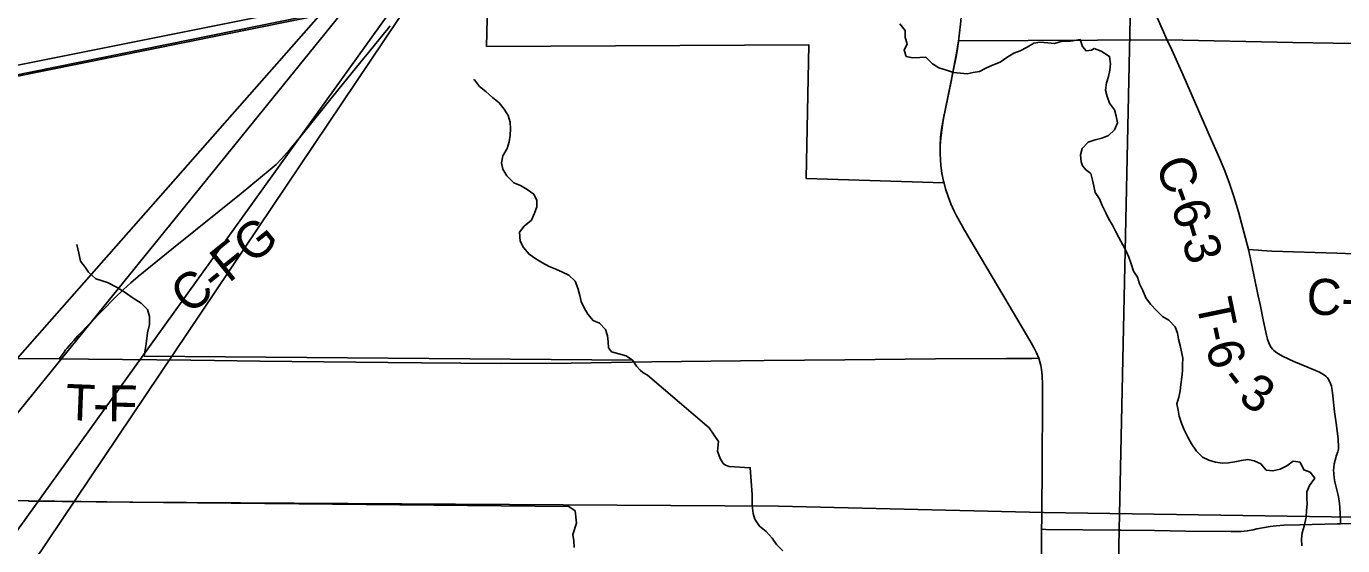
# Model space of a CAD drawing. Extents: x -21.7 to 34, y 0 to 22.
# Drawn here: x 25.914 to 27.989, y 16.19 to 17.008 of the extents above; entities that cross this region are included whole.
import ezdxf

# ---------------------------------------------------------------- set-up
doc = ezdxf.new("R2010")
doc.units = 0
for name, color, linetype in [('GM_X_Corporation', 7, 'Continuous'), ('GM_X_County_Road', 7, 'Continuous'), ('GM_X_County_Road_Text', 7, 'Continuous'), ('GM_X_Interchange_Ramps', 7, 'Continuous'), ('GM_X_Minor_River', 7, 'Continuous'), ('GM_X_Rail_Line', 7, 'Continuous'), ('GM_X_State_Route', 7, 'Continuous'), ('GM_X_Township_Road', 7, 'Continuous'), ('GM_X_Township_Road_Text', 7, 'Continuous'), ('SH_Text', 7, 'Continuous')]:
    doc.layers.add(name, color=color, linetype=linetype)

msp = doc.modelspace()

# ---------------------------------------------------------------- linework, layer by layer
at = {"layer": 'GM_X_Corporation'}
msp.add_lwpolyline([(28.8958, 16.966), (27.9107, 16.9822), (27.7126, 16.9865), (27.3835, 16.9849), (27.3796, 16.9596), (27.3715, 16.9192), (27.3594, 16.8603), (27.3572, 16.8458), (27.3556, 16.8325), (27.3548, 16.82), (27.3546, 16.8075), (27.3557, 16.7888), (27.3575, 16.7765), (27.3607, 16.7612), (27.1434, 16.7683), (27.148, 16.9785), (26.6397, 16.9761), (26.6452, 17.1938)], dxfattribs=at)
at = {"layer": 'GM_X_County_Road'}
for points in [[(27.7128, 16.9859), (27.6888, 17.0394), (27.6756, 17.0676), (27.6712, 17.0758), (27.6677, 17.0811), (27.6658, 17.0835), (27.6636, 17.0859), (27.656, 17.0933)], [(25.966, 16.4842), (25.9737, 16.4944), (25.9762, 16.498), (25.9789, 16.501), (25.9814, 16.5039), (25.9852, 16.5081), (25.9891, 16.513), (25.9953, 16.52), (26.054, 16.5802), (26.0674, 16.5932), (26.0789, 16.6037), (26.0908, 16.6138), (26.1271, 16.6431), (26.1463, 16.6589), (26.253, 16.7446), (26.2987, 16.782), (26.3079, 16.7903), (26.3166, 16.7991), (26.3289, 16.8131), (26.3448, 16.8322), (26.3858, 16.883), (26.4074, 16.9096), (26.4465, 16.9578), (26.4543, 16.967), (26.4788, 16.9973), (26.4827, 17.0017), (26.4876, 17.0083)], [(27.8411, 16.6564), (27.8251, 16.7156), (27.8179, 16.7395), (27.8109, 16.76), (27.8038, 16.7801), (27.7954, 16.8), (27.7824, 16.8284), (27.7626, 16.8741), (27.7381, 16.9308), (27.7203, 16.9706), (27.7128, 16.9859)], [(27.8411, 16.6564), (27.8559, 16.6551), (27.862, 16.6544), (27.8775, 16.6536), (27.9799, 16.6504), (28.0482, 16.6479), (28.0855, 16.6464), (28.2779, 16.6398), (28.3959, 16.636), (28.4673, 16.6333), (28.5636, 16.63), (28.5729, 16.6293), (28.5791, 16.6283), (28.5852, 16.6268), (28.5912, 16.6248), (28.5969, 16.6222), (28.6052, 16.6177), (28.6238, 16.6065), (28.6423, 16.595)], [(25.6331, 16.4875), (25.6723, 16.4872), (25.8993, 16.4845), (25.966, 16.4842)]]:
    msp.add_lwpolyline(points, dxfattribs=at)
at = {"layer": 'GM_X_Interchange_Ramps'}
for points in [[(27.6229, 15.4779), (27.6372, 16.2146), (27.6557, 17.0939)], [(27.6557, 17.0939), (27.6372, 16.2146), (27.6229, 15.4779)]]:
    msp.add_lwpolyline(points, dxfattribs=at)
at = {"layer": 'GM_X_Minor_River'}
for points in [[(27.2913, 17.0115), (27.2998, 17.0011), (27.2999, 16.9901), (27.3027, 16.9801), (27.2983, 16.97), (27.3015, 16.9604), (27.312, 16.9583), (27.3227, 16.9588), (27.3322, 16.959), (27.3429, 16.9485), (27.3527, 16.9422), (27.3662, 16.9381), (27.376, 16.9349), (27.387, 16.9342), (27.3972, 16.9329), (27.4071, 16.9349), (27.417, 16.9366), (27.427, 16.9417)], [(27.427, 16.9417), (27.4374, 16.9468), (27.4492, 16.9514), (27.46, 16.9588), (27.4708, 16.9654), (27.4811, 16.9689), (27.4919, 16.9751), (27.5027, 16.981), (27.5122, 16.983), (27.5247, 16.9816), (27.5353, 16.9806), (27.5456, 16.9838), (27.5608, 16.9846), (27.5753, 16.987), (27.5792, 16.9759), (27.585, 16.969), (27.5934, 16.97)], [(27.588, 16.8251), (27.5991, 16.8291), (27.6098, 16.8315), (27.6201, 16.8359), (27.6297, 16.8448), (27.6345, 16.8557), (27.6324, 16.866), (27.6296, 16.8763), (27.6218, 16.8867), (27.6183, 16.897), (27.6154, 16.907), (27.6172, 16.9187), (27.62, 16.9289), (27.6221, 16.9387), (27.6231, 16.9489), (27.6218, 16.9604), (27.6087, 16.9686), (27.5974, 16.973), (27.5934, 16.97)], [(26.8318, 16.5014), (26.8316, 16.5109), (26.8303, 16.5204), (26.8271, 16.5304), (26.8178, 16.5401), (26.8077, 16.5445), (26.7992, 16.5545), (26.7934, 16.5645), (26.7887, 16.5741), (26.7866, 16.584), (26.7835, 16.5951), (26.7795, 16.6062), (26.7695, 16.6156), (26.7594, 16.6203), (26.7489, 16.6255), (26.7387, 16.6295), (26.7279, 16.6351), (26.7174, 16.6414), (26.7069, 16.6488), (26.6981, 16.6593), (26.6926, 16.6693), (26.6918, 16.6833), (26.6992, 16.693), (26.7108, 16.7026), (26.7153, 16.7136), (26.7193, 16.7237), (26.7188, 16.7336), (26.7144, 16.7432), (26.704, 16.751), (26.6931, 16.7569), (26.6826, 16.7613), (26.6715, 16.7722), (26.6657, 16.783), (26.6636, 16.7929), (26.6654, 16.8039), (26.6721, 16.8151), (26.6754, 16.826), (26.6771, 16.8362), (26.6774, 16.8461), (26.6768, 16.8567), (26.6737, 16.8671), (26.6675, 16.8771), (26.6597, 16.8871), (26.6493, 16.8957), (26.6385, 16.905), (26.6288, 16.9132), (26.6207, 16.9237), (26.6192, 16.9241)], [(27.588, 16.8251), (27.5788, 16.8155), (27.5763, 16.8053), (27.5773, 16.7945), (27.5794, 16.788), (27.5827, 16.7838)], [(27.8399, 16.3257), (27.8297, 16.324), (27.8194, 16.322), (27.8095, 16.3203), (27.7997, 16.3197), (27.7887, 16.3214), (27.7785, 16.3243), (27.7684, 16.3291), (27.7591, 16.3387), (27.751, 16.3499), (27.7452, 16.3607), (27.7397, 16.3722), (27.7354, 16.3829), (27.7318, 16.3936), (27.7301, 16.4031), (27.728, 16.413), (27.7313, 16.4236), (27.7334, 16.4338), (27.7343, 16.4436), (27.7357, 16.455), (27.7366, 16.4649), (27.7368, 16.4744), (27.7374, 16.485), (27.7353, 16.4953), (27.7333, 16.5052), (27.7308, 16.5151), (27.7291, 16.5246), (27.7251, 16.5342), (27.7151, 16.545), (27.7054, 16.5505), (27.6961, 16.5602), (27.6864, 16.5699), (27.679, 16.5799), (27.6744, 16.5918), (27.6689, 16.6021), (27.6657, 16.6125), (27.6598, 16.6221), (27.6559, 16.6335), (27.6523, 16.6442), (27.6479, 16.6538), (27.6428, 16.6634), (27.6366, 16.6749), (27.6315, 16.6849), (27.6264, 16.6945), (27.6209, 16.7041), (27.6162, 16.7141), (27.6103, 16.7256), (27.606, 16.7363), (27.599, 16.7459), (27.5973, 16.7558), (27.5952, 16.7654), (27.5924, 16.7757), (27.5839, 16.7822), (27.5827, 16.7838)], [(26.8696, 16.482), (26.1003, 16.4882), (26.1004, 16.492), (26.1031, 16.5079), (26.1053, 16.5249), (26.1087, 16.5381), (26.1086, 16.5506), (26.1054, 16.5617), (26.0951, 16.5718), (26.0827, 16.5797), (26.07, 16.5887), (26.0573, 16.5966), (26.0423, 16.6041), (26.0239, 16.6102), (26.0123, 16.6203), (26.0072, 16.6284), (25.9998, 16.6381), (25.9971, 16.6503), (25.994, 16.664)], [(26.8599, 16.4887), (26.8369, 16.4953), (26.8318, 16.5014)], [(27.0586, 16.2705), (27.0554, 16.3124), (27.0221, 16.3146), (27.0164, 16.3163), (27.0127, 16.3194), (27.0083, 16.3271), (27.0036, 16.3386), (27.0055, 16.3537), (26.9985, 16.3637), (26.9905, 16.3753), (26.8934, 16.4583), (26.8862, 16.4623), (26.8818, 16.4662), (26.8759, 16.4727), (26.8696, 16.482), (26.8599, 16.4887)], [(27.9248, 16.1896), (27.9242, 16.1999), (27.9255, 16.2097), (27.9284, 16.2203), (27.9317, 16.2347), (27.9323, 16.2449), (27.9333, 16.2551), (27.9327, 16.2646), (27.9329, 16.2745), (27.9369, 16.2843), (27.9454, 16.2959), (27.938, 16.3055), (27.9279, 16.3091), (27.9221, 16.3214), (27.9115, 16.3228), (27.9011, 16.3154), (27.8908, 16.3103), (27.8794, 16.3075), (27.8688, 16.3084), (27.8606, 16.3185), (27.8498, 16.3236), (27.8399, 16.3257)], [(27.1066, 16.1818), (27.097, 16.1915), (27.09, 16.2015), (27.0807, 16.212), (27.0699, 16.2206), (27.0627, 16.2315), (27.06, 16.2406), (27.0586, 16.2529), (27.0586, 16.2705)], [(26.7694, 16.2512), (25.9178, 16.2596)], [(26.7778, 16.1869), (26.7773, 16.1975), (26.7756, 16.2074), (26.7815, 16.2254), (26.7797, 16.2445), (26.7694, 16.2512)]]:
    msp.add_lwpolyline(points, dxfattribs=at)
at = {"layer": 'GM_X_Rail_Line'}
for points in [[(23.5167, 16.459), (23.6295, 16.4808), (23.9621, 16.5465), (24.6321, 16.6797), (25.2774, 16.8081), (25.8901, 16.9293), (26.3845, 17.0293), (27.0776, 17.1675), (27.7467, 17.2984), (28.3715, 17.4275), (28.9889, 17.5495), (29.6221, 17.6814), (30.2791, 17.8098), (30.3167, 17.8172)], [(23.5167, 16.4567), (23.6289, 16.4784), (23.9619, 16.5433), (24.6317, 16.6775), (25.2779, 16.8058), (25.8906, 16.927), (26.3849, 17.0271), (27.078, 17.1653), (27.7471, 17.2961), (28.3719, 17.4252), (28.9894, 17.5472), (29.6225, 17.6791), (30.2796, 17.8076), (30.3167, 17.8149)], [(25.8905, 16.9443), (26.7077, 17.1083), (26.7688, 17.1586), (26.8119, 17.2101), (26.8634, 17.276), (26.8946, 17.3324), (26.9509, 17.3923), (27.006, 17.4474), (27.0347, 17.4689), (27.0802, 17.4809), (27.5534, 17.4838), (27.9584, 17.4827), (28.1647, 17.4796), (28.575, 17.4796), (29.0617, 17.5773), (30.0904, 17.7802), (30.3167, 17.8248)], [(25.8774, 16.2608), (26.0821, 16.258), (27.0998, 16.252), (27.5176, 16.2418), (28.8453, 16.222), (29.9847, 16.211), (30.3167, 16.2074)]]:
    msp.add_lwpolyline(points, dxfattribs=at)
at = {"layer": 'GM_X_State_Route'}
for points in [[(27.3836, 16.9834), (27.3837, 16.9844), (27.3848, 16.9929), (27.3872, 17.0161), (27.3903, 17.05), (27.3947, 17.0931), (27.3972, 17.1183), (27.3992, 17.1411)], [(27.3755, 16.9374), (27.3795, 16.9572), (27.3821, 16.9725), (27.3832, 16.9807), (27.3836, 16.9834)], [(27.3609, 16.7607), (27.3602, 16.7637), (27.3577, 16.7759), (27.356, 16.7883), (27.3552, 16.7976), (27.3548, 16.807), (27.355, 16.8195), (27.3558, 16.8319), (27.3573, 16.8443), (27.3597, 16.8597), (27.3632, 16.878), (27.3721, 16.9206), (27.3755, 16.9374)], [(27.3808, 16.709), (27.3768, 16.7167), (27.3717, 16.728), (27.3672, 16.7397), (27.3633, 16.7516), (27.3609, 16.7607)], [(27.4566, 16.5798), (27.4535, 16.5849), (27.3931, 16.6865), (27.3825, 16.7056), (27.3808, 16.709)], [(27.5148, 16.2194), (27.5149, 16.2281), (27.5158, 16.3307), (27.5163, 16.4053), (27.5162, 16.4426), (27.5156, 16.4581), (27.5147, 16.4673), (27.5136, 16.4734), (27.5121, 16.4793), (27.5103, 16.4849), (27.5066, 16.4937), (27.5025, 16.502), (27.4964, 16.5128), (27.4566, 16.5798)], [(27.514, 16.1162), (27.5148, 16.2155), (27.5148, 16.2194)]]:
    msp.add_lwpolyline(points, dxfattribs=at)
at = {"layer": 'GM_X_Township_Road'}
for points in [[(27.9858, 16.2242), (27.9857, 16.2294), (27.9856, 16.2386), (27.9849, 16.251), (27.9837, 16.2602), (27.982, 16.2693), (27.977, 16.2905), (27.9759, 16.2967), (27.9752, 16.303), (27.975, 16.3093), (27.9752, 16.3124), (27.9762, 16.3187), (27.9784, 16.3279), (27.9793, 16.3308), (27.9817, 16.3375), (27.9824, 16.3397), (27.9828, 16.3423), (27.9829, 16.3453), (27.982, 16.3576), (27.9794, 16.3791), (27.9765, 16.4008), (27.9737, 16.4256), (27.9726, 16.4348), (27.9715, 16.4409), (27.9707, 16.4438), (27.9696, 16.4466), (27.9683, 16.4494), (27.9668, 16.452), (27.965, 16.4544), (27.9629, 16.4565), (27.9606, 16.4585), (27.9581, 16.4601), (27.9527, 16.4629), (27.9327, 16.4714), (27.9125, 16.4799), (27.8958, 16.4875), (27.8906, 16.4902), (27.8857, 16.4934), (27.8809, 16.497), (27.8786, 16.4992), (27.8765, 16.5017), (27.8748, 16.5047), (27.8727, 16.5094), (27.8708, 16.5152), (27.8691, 16.5215), (27.8646, 16.543), (27.8591, 16.5695), (27.8554, 16.5854), (27.8455, 16.6343), (27.8411, 16.6564)], [(25.6331, 16.4875), (25.6723, 16.4872), (25.8993, 16.4845), (25.966, 16.4842)], [(25.966, 16.4842), (26.0122, 16.4835), (26.1737, 16.4818), (26.2109, 16.4814), (26.2824, 16.4805), (26.4843, 16.478), (26.5371, 16.4777), (26.6613, 16.4769), (26.7731, 16.4774), (26.9005, 16.4794), (27.0402, 16.481), (27.0775, 16.4814), (27.2048, 16.4826), (27.3477, 16.4842), (27.4595, 16.4844), (27.4999, 16.4848), (27.5103, 16.4849)], [(27.5148, 16.2155), (27.5215, 16.2154), (27.6374, 16.214)], [(27.6374, 16.214), (27.6397, 16.214), (27.6925, 16.2134), (27.7423, 16.2126), (27.8138, 16.212), (27.8294, 16.2123), (27.8388, 16.213), (27.848, 16.2146), (27.854, 16.2161), (27.8753, 16.2199), (27.8845, 16.2211), (27.8968, 16.2219), (27.9217, 16.2225), (27.9807, 16.2242), (27.9858, 16.2242)], [(27.9858, 16.2242), (28.0118, 16.2245), (28.105, 16.2234), (28.1734, 16.2227), (28.2107, 16.2221), (28.3351, 16.2209), (28.447, 16.2191), (28.5402, 16.2173), (28.6148, 16.216), (28.6345, 16.216)]]:
    msp.add_lwpolyline(points, dxfattribs=at)
at = {"layer": 'SH_Text'}
for points in [[(23.5845, 13.5445), (26.7756, 17.4787), (23.5845, 13.8593)], [(23.5845, 12.6836), (26.8092, 17.4787), (23.5845, 12.9954)]]:
    msp.add_lwpolyline(points, close=True, dxfattribs=at)

# ---------------------------------------------------------------- texts
at = {"layer": 'GM_X_County_Road_Text'}
for s, height, rotation, p in [('C', 0.0568, 292.7328, (27.6928, 16.7894)), ('-', 0.0568, 290.1212, (27.7106, 16.747)), ('6', 0.0568, 286.9948, (27.7183, 16.7258)), ('C-FG', 0.05682, 38.8016, (26.171, 16.5523)), ('-', 0.0568, 286.771, (27.7286, 16.6924)), ('3', 0.0568, 286.7282, (27.7353, 16.6701)), ('C-F', 0.05682, 357.7986, (27.9316, 16.5542))]:
    msp.add_text(s, height=height, rotation=rotation, dxfattribs=at).set_placement(p)
at = {"layer": 'GM_X_Township_Road_Text'}
for s, rotation, p in [('T', 281.7125, (27.758, 16.5737)), ('-', 281.968, (27.7666, 16.5318)), ('6', 286.054, (27.7725, 16.5047)), ('-', 307.8468, (27.7928, 16.4502)), ('3', 327.304, (27.8226, 16.4177)), ('T', 357.758, (25.9754, 16.3878)), ('F', 359.296, (26.0429, 16.3857)), ('-', 358.9555, (26.0192, 16.3861))]:
    msp.add_text(s, height=0.0568, rotation=rotation, dxfattribs=at).set_placement(p)

doc.saveas('drawing.dxf')
